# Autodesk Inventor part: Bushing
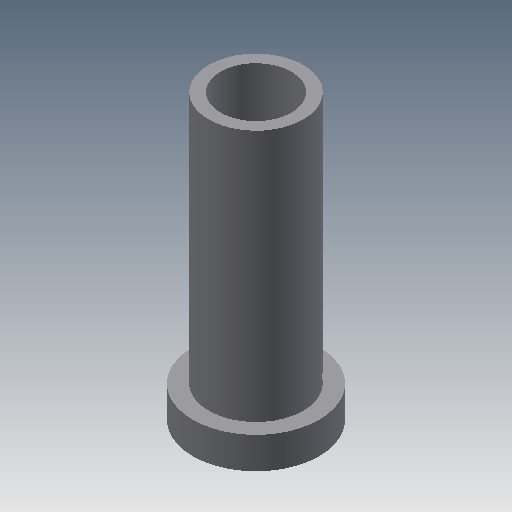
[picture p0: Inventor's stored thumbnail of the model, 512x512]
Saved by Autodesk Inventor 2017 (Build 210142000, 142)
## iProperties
Shininess: 77.0
Length Units: 11269
Angle Units: 11279
Time Units: 11290
Mass Units: 11283
Length Display Precision: 3
Angle Display Precision: 2
Created: 2002-02
Part Number: Bushing
Document SubType Name: Modeling
Designer: ***
Density: 1 g/cm^3
Material: Generic
Appearance: Default
Density: 0.0
Volumn: 0.0
Area: 0.0
PropertySet Name: Model Information
Control State: 0
Master: False
Checked Out: False
Author: ***
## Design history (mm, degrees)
sketch "Sketch1"
  geometry: L1 (6.25, 50.44)-(6.25, 5.44); L2 (6.25, 5.44)-(10.625, 5.44); L3 (10.625, 5.44)-(10.625, 10.44); L4 (10.625, 10.44)-(8.125, 10.44); L5 (8.125, 10.44)-(8.125, 50.44); L6 (8.125, 50.44)-(6.25, 50.44); L7 (0.625, 34.884)-(0.625, 0)
  constraints: 14 end point, 4 parallel, 2 perpendicular, 1 vertical
  dimensions: "d0" = 20 diameter of L3 L7; "d1" = 11.25 diameter of L1 L7; "d2" = 15 diameter of L5 L7; "d4" = 5 distance of L2.end L3.end; "d5" = 45 distance of L1.start L1.end
revolve "Revolution1" sketch "Sketch1" stored, may be unused: angle "d3" = 90 deg
body "Solid1"
